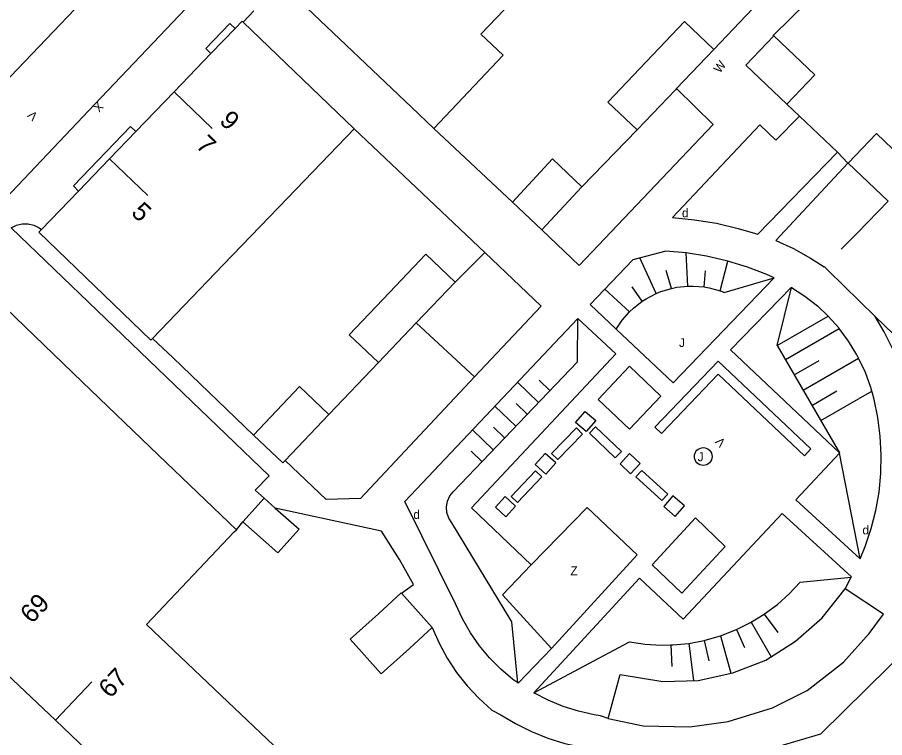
# Model space of a CAD drawing. Extents: x 134999 to 136502, y 457398 to 459002.
# Drawn here: x 135044.97 to 135094.16, y 458158.26 to 458199.12 of the extents above; entities that cross this region are included whole.
import ezdxf

# ---------------------------------------------------------------- set-up
doc = ezdxf.new("R2010")
doc.units = 0
for name, color, linetype in [('RI_DGTB_15', 7, 'Continuous'), ('RI_DGTB_18', 7, 'Continuous'), ('RI_DGTB_19', 7, 'Continuous'), ('RI_DGTB_2', 7, 'Continuous'), ('RI_DGTB_29', 7, 'Continuous'), ('RI_DGTB_30', 7, 'Continuous'), ('RI_DGTB_31', 7, 'Continuous'), ('RI_DGTB_32', 7, 'Continuous'), ('RI_DGTB_35', 7, 'Continuous'), ('RI_DGTB_36', 7, 'Continuous'), ('RI_DGTB_48', 7, 'Continuous'), ('RI_DGTB_5', 7, 'Continuous'), ('RI_DGTB_53', 7, 'Continuous'), ('RI_DGTB_54', 7, 'Continuous'), ('RI_DGTB_6', 7, 'Continuous'), ('RI_DGTB_7', 7, 'Continuous')]:
    doc.layers.add(name, color=color, linetype=linetype)

msp = doc.modelspace()

# ---------------------------------------------------------------- linework, layer by layer
at = {"layer": 'RI_DGTB_15'}
for p, q in [((135053.866, 458194.902), (135056.028, 458192.822)), ((135050.201, 458191.094), (135052.363, 458189.014)), ((135047.126, 458159.25), (135049.195, 458161.424))]:
    msp.add_line(p, q, dxfattribs=at)
at = {"layer": 'RI_DGTB_18'}
for p, q in [((135082.998, 458183.874), (135082.894, 458185.756)), ((135081.195, 458183.452), (135080.273, 458185.473)), ((135084.826, 458183.607), (135085.257, 458185.293)), ((135082.075, 458183.747), (135081.761, 458184.765)), ((135083.929, 458183.826), (135083.992, 458184.741)), ((135080.409, 458183.014), (135079.83, 458183.826)), ((135088.065, 458180.507), (135088.877, 458183.806)), ((135079.689, 458182.415), (135078.287, 458183.698)), ((135088.065, 458180.507), (135090.949, 458182.176)), ((135088.53, 458179.704), (135091.579, 458181.469)), ((135088.065, 458180.507), (135091.588, 458174.421)), ((135089.031, 458178.839), (135090.442, 458179.656)), ((135089.532, 458177.973), (135092.68, 458179.795)), ((135074.527, 458177.277), (135073.332, 458178.421)), ((135075.169, 458177.948), (135074.558, 458178.532)), ((135090.033, 458177.108), (135091.444, 458177.925)), ((135090.534, 458176.242), (135093.437, 458177.922)), ((135073.244, 458175.936), (135072.058, 458177.071)), ((135073.886, 458176.607), (135073.254, 458177.212)), ((135071.962, 458174.595), (135070.784, 458175.722)), ((135072.603, 458175.266), (135071.977, 458175.865)), ((135071.32, 458173.925), (135070.703, 458174.515)), ((135092.77, 458168.41), (135091.602, 458174.391)), ((135087.325, 458165.26), (135088.106, 458164.233)), ((135086.59, 458164.808), (135087.722, 458162.85)), ((135085.764, 458164.392), (135086.218, 458163.376)), ((135083.048, 458163.609), (135083.314, 458161.492)), ((135083.926, 458163.774), (135084.178, 458162.618)), ((135084.841, 458164.033), (135085.432, 458161.916)), ((135082.035, 458163.516), (135082.085, 458162.304))]:
    msp.add_line(p, q, dxfattribs=at)
for points in [[(135078.93, 458181.431), (135079.273, 458181.939), (135079.689, 458182.415), (135079.907, 458182.621), (135080.409, 458183.014), (135080.639, 458183.162), (135081.195, 458183.452), (135081.471, 458183.564), (135082.075, 458183.747), (135082.37, 458183.807), (135082.998, 458183.874), (135083.303, 458183.878), (135083.929, 458183.826), (135084.214, 458183.775), (135084.826, 458183.607), (135084.944, 458183.565), (135085.06, 458183.52), (135087.89, 458184.35)], [(135073.355, 458161.361), (135073.01, 458164.82), (135069.61, 458170.44), (135069.437, 458170.718), (135069.336, 458171.029), (135069.313, 458171.355), (135069.37, 458171.678), (135069.503, 458171.977), (135069.68, 458172.21), (135076.73, 458179.581), (135076.76, 458182.03)], [(135091.602, 458174.391), (135091.6, 458174.4), (135091.588, 458174.421)], [(135074.26, 458160.81), (135079.69, 458163.69), (135080.582, 458163.559), (135081.482, 458163.508), (135082.035, 458163.516), (135082.145, 458163.521), (135083.048, 458163.609), (135083.926, 458163.774), (135083.971, 458163.785), (135084.841, 458164.033), (135084.935, 458164.065), (135085.764, 458164.392), (135086.556, 458164.787), (135087.325, 458165.26), (135087.347, 458165.275), (135088.071, 458165.817), (135088.743, 458166.42), (135089.36, 458167.08), (135092.258, 458167.358)]]:
    msp.add_lwpolyline(points, dxfattribs=at)
at = {"layer": 'RI_DGTB_19'}
msp.add_lwpolyline([(135074.11, 458168.07), (135072.48, 458166.36), (135075.266, 458163.325)], dxfattribs=at)
at = {"layer": 'RI_DGTB_2'}
for p, q in [((135073.009, 458200), (135071.265, 458198.165)), ((135064.079, 458192.794), (135057.779, 458198.858)), ((135064.079, 458192.794), (135060.316, 458188.885)), ((135060.316, 458188.885), (135056.651, 458185.077)), ((135052.628, 458180.898), (135056.651, 458185.077)), ((135044.31, 458182.62), (135048.653, 458178.447)), ((135048.653, 458178.447), (135052.98, 458174.289)), ((135052.98, 458174.289), (135057.39, 458170.051)), ((135056.537, 458160.646), (135052.29, 458164.67)), ((135060.782, 458156.624), (135056.537, 458160.646)), ((135051.361, 458155.215), (135047.126, 458159.25))]:
    msp.add_line(p, q, dxfattribs=at)
for points in [[(135061.038, 458200), (135067.327, 458194.022)], [(135057.779, 458198.858), (135057.724, 458198.911), (135057.321, 458198.493)], [(135057.321, 458198.493), (135055.949, 458197.066)], [(135055.949, 458197.066), (135053.866, 458194.902)], [(135051.694, 458192.646), (135053.866, 458194.902)], [(135050.201, 458191.094), (135051.694, 458192.646)], [(135050.201, 458191.094), (135048.442, 458189.266)], [(135048.442, 458189.266), (135046.341, 458187.084)], [(135052.628, 458180.898), (135052.549, 458180.816), (135046.194, 458186.931), (135046.341, 458187.084)], [(135052.29, 458164.67), (135057.27, 458169.93), (135057.39, 458170.051)], [(135047.126, 458159.25), (135044.381, 458161.867)]]:
    msp.add_lwpolyline(points, dxfattribs=at)
at = {"layer": 'RI_DGTB_31'}
for points in [[(135077.23, 458175.62), (135076.63, 458176.14), (135077.18, 458176.77), (135077.78, 458176.25), (135077.23, 458175.62)], [(135074.94, 458173.21), (135075.51, 458173.84), (135074.91, 458174.38), (135074.34, 458173.75), (135074.94, 458173.21)], [(135079.69, 458174.37), (135079.15, 458173.79), (135079.75, 458173.23), (135080.29, 458173.81), (135079.69, 458174.37)], [(135082.15, 458171.97), (135081.63, 458171.37), (135082.28, 458170.81), (135082.8, 458171.41), (135082.15, 458171.97)], [(135072.68, 458170.79), (135073.23, 458171.4), (135072.63, 458171.94), (135072.08, 458171.33), (135072.68, 458170.79)]]:
    msp.add_lwpolyline(points, dxfattribs=at)
msp.add_circle((135083.868, 458174.207), 0.504, dxfattribs=at)
at = {"layer": 'RI_DGTB_32'}
for points in [[(135077.42, 458175.54), (135078.88, 458174.13), (135079.227, 458174.49), (135077.767, 458175.9), (135077.42, 458175.54)], [(135075.62, 458174.03), (135077.03, 458175.48), (135076.672, 458175.829), (135075.262, 458174.379), (135075.62, 458174.03)], [(135073.33, 458171.59), (135074.72, 458173.05), (135074.358, 458173.395), (135072.968, 458171.935), (135073.33, 458171.59)], [(135080.05, 458173.05), (135081.52, 458171.71), (135081.857, 458172.08), (135080.387, 458173.42), (135080.05, 458173.05)]]:
    msp.add_lwpolyline(points, dxfattribs=at)
at = {"layer": 'RI_DGTB_48'}
msp.add_line((135057.39, 458170.051), (135057.76, 458170.5), dxfattribs=at)
for points in [[(135092.592, 458186.878), (135094.362, 458188.693)], [(135092.592, 458186.878), (135091.7, 458185.964)], [(135099.55, 458183.78), (135098.36, 458184.88), (135094.66, 458181.14), (135093.62, 458182.16)]]:
    msp.add_lwpolyline(points, dxfattribs=at)
at = {"layer": 'RI_DGTB_5'}
for points in [[(135071.265, 458198.165), (135072.523, 458196.969), (135068.585, 458192.826)], [(135068.585, 458192.826), (135067.327, 458194.022)]]:
    msp.add_lwpolyline(points, dxfattribs=at)
at = {"layer": 'RI_DGTB_53'}
for p, q in [((135087.045, 458200), (135084.473, 458197.3)), ((135057.779, 458198.858), (135058.39, 458199.49)), ((135089.335, 458193.524), (135088.604, 458194.197)), ((135091.49, 458191.47), (135089.335, 458193.524)), ((135064.079, 458192.794), (135071.49, 458185.79)), ((135071.49, 458185.79), (135069.802, 458184.101)), ((135090.777, 458184.925), (135090.73, 458184.97)), ((135067.595, 458181.785), (135070.89, 458178.72)), ((135062.642, 458176.585), (135065.449, 458179.533)), ((135091.91, 458166.71), (135092.258, 458167.358))]:
    msp.add_line(p, q, dxfattribs=at)
for points in [[(135054.883, 458200), (135049.37, 458194.19), (135043.29, 458187.81), (135040, 458190.93), (135040.72, 458191.66), (135040.743, 458191.685)], [(135048.629, 458200), (135042.55, 458193.64), (135040.743, 458191.685)], [(135087.879, 458198.071), (135087.84, 458198.1), (135089.778, 458200)], [(135082.359, 458195.081), (135084.43, 458193.05), (135076.83, 458185.05), (135074.715, 458187.06)], [(135089.335, 458193.524), (135087.98, 458192.15), (135087.08, 458193.03), (135082.12, 458187.77), (135083.375, 458187.643), (135084.62, 458187.437), (135085.85, 458187.152), (135086.97, 458186.82), (135091.49, 458191.47)], [(135068.585, 458192.826), (135073.045, 458188.631)], [(135091.49, 458191.47), (135092.07, 458190.85), (135087.98, 458186.46), (135088.983, 458186), (135089.95, 458185.469), (135090.73, 458184.97)], [(135044.622, 458187.175), (135044.92, 458187.331), (135045.245, 458187.412), (135045.581, 458187.414), (135045.908, 458187.337), (135046.208, 458187.185), (135046.341, 458187.084)], [(135044.622, 458187.175), (135059.26, 458173.12), (135058.45, 458172.29), (135058.96, 458171.84)], [(135071.49, 458185.79), (135074.68, 458182.73), (135070.89, 458178.72)], [(135087.89, 458184.35), (135087.474, 458184.532), (135086.379, 458184.95), (135085.257, 458185.293), (135085.191, 458185.311), (135084.05, 458185.573), (135082.894, 458185.756), (135081.75, 458185.86), (135079.88, 458185.37), (135077.46, 458182.83), (135078.93, 458181.431)], [(135093.62, 458182.16), (135090.949, 458184.758)], [(135087.89, 458184.35), (135082.17, 458178.38), (135078.93, 458181.431)], [(135091.588, 458174.421), (135085.42, 458180.26), (135088.87, 458183.81), (135088.877, 458183.806)], [(135088.877, 458183.806), (135089.632, 458183.31), (135090.341, 458182.749), (135090.949, 458182.176)], [(135099.55, 458183.78), (135095.06, 458179.22), (135094.634, 458180.264), (135094.135, 458181.274), (135093.62, 458182.16)], [(135073.355, 458161.361), (135073.079, 458161.564), (135072.389, 458162.142), (135071.753, 458162.779), (135071.175, 458163.47), (135070.661, 458164.209), (135070.215, 458164.991), (135069.84, 458165.81), (135066.94, 458171.65), (135076.75, 458182.04), (135076.76, 458182.03)], [(135076.76, 458182.03), (135078.91, 458180.03), (135070.72, 458171.29), (135074.11, 458168.07)], [(135092.77, 458168.41), (135093.058, 458169.112), (135093.395, 458170.117), (135093.657, 458171.144), (135093.839, 458172.188), (135093.943, 458173.243), (135093.967, 458174.302), (135093.911, 458175.361), (135093.775, 458176.412), (135093.56, 458177.45), (135093.53, 458177.58), (135093.485, 458177.751), (135093.437, 458177.922), (135093.374, 458178.128), (135093.064, 458178.977), (135092.68, 458179.795), (135092.584, 458179.974), (135092.115, 458180.744), (135091.579, 458181.469), (135091.552, 458181.502), (135090.949, 458182.176)], [(135058.364, 458175.427), (135053.8, 458179.8), (135052.628, 458180.898)], [(135079.69, 458175.76), (135077.91, 458177.45), (135079.68, 458179.33), (135081.46, 458177.64), (135079.69, 458175.76)], [(135081.5, 458175.51), (135081.13, 458175.87), (135084.71, 458179.62), (135089.98, 458174.65), (135089.62, 458174.25), (135084.71, 458178.88), (135081.5, 458175.51)], [(135070.89, 458178.72), (135064.43, 458171.83), (135062.48, 458171.76), (135060.165, 458173.985)], [(135091.602, 458174.391), (135091.61, 458174.4), (135091.588, 458174.421)], [(135092.77, 458168.41), (135089.12, 458171.75), (135091.602, 458174.391)], [(135066.759, 458166.449), (135067.43, 458166.94), (135066.65, 458168.37), (135065.63, 458169.98), (135059.594, 458171.279)], [(135074.11, 458168.07), (135077.28, 458171.32), (135080.12, 458168.63), (135075.266, 458163.325)], [(135092.258, 458167.358), (135092.27, 458167.38), (135088.34, 458170.98), (135082.73, 458164.98), (135080.26, 458167.31), (135074.26, 458160.81)], [(135080.97, 458168.07), (135082.66, 458166.45), (135085.12, 458169.1), (135083.43, 458170.72), (135080.97, 458168.07)], [(135068.49, 458164.5), (135068.884, 458163.616), (135069.35, 458162.767), (135069.884, 458161.959), (135070.483, 458161.198), (135071.143, 458160.49), (135071.88, 458159.82), (135072.36, 458159.57), (135073.222, 458159.053), (135074.122, 458158.607), (135075.055, 458158.233), (135076.014, 458157.935), (135076.994, 458157.714), (135077.989, 458157.571), (135078.397, 458157.536)], [(135075.266, 458163.325), (135073.37, 458161.35), (135073.355, 458161.361)], [(135090.786, 458149.537), (135090.034, 458150.255), (135090.069, 458150.292), (135083.61, 458156.44), (135090.54, 458158.47), (135095.71, 458163.58), (135099.104, 458160.394), (135099.17, 458160.46), (135100.246, 458159.434)], [(135078.47, 458159.35), (135078.04, 458159.5), (135077.683, 458159.557), (135076.789, 458159.757), (135075.917, 458160.034), (135075.071, 458160.386), (135074.26, 458160.81)]]:
    msp.add_lwpolyline(points, dxfattribs=at)
at = {"layer": 'RI_DGTB_54'}
msp.add_line((135076.99, 458189.517), (135080.12, 458192.732), dxfattribs=at)
at = {"layer": 'RI_DGTB_6'}
for p, q in [((135082.359, 458195.081), (135084.473, 458197.3)), ((135082.359, 458195.081), (135082.296, 458195.015)), ((135074.715, 458187.06), (135076.99, 458189.517)), ((135073.045, 458188.631), (135074.715, 458187.06)), ((135066.068, 458183.515), (135068.137, 458185.687)), ((135069.802, 458184.101), (135067.595, 458181.785)), ((135067.595, 458181.785), (135065.449, 458179.533)), ((135060.165, 458173.985), (135062.642, 458176.585)), ((135057.76, 458170.5), (135058.96, 458171.84)), ((135058.96, 458171.84), (135059.594, 458171.279)), ((135068.49, 458164.5), (135066.759, 458166.449))]:
    msp.add_line(p, q, dxfattribs=at)
for points in [[(135084.473, 458197.3), (135082.807, 458198.887), (135080.63, 458196.603)], [(135087.879, 458198.071), (135086.291, 458196.408), (135088.604, 458194.197)], [(135088.604, 458194.197), (135090.192, 458195.86), (135087.879, 458198.071)], [(135080.63, 458196.603), (135078.454, 458194.319), (135080.12, 458192.732)], [(135080.12, 458192.732), (135082.296, 458195.015)], [(135094.362, 458188.693), (135092.095, 458190.859), (135093.691, 458192.53), (135095.964, 458190.358)], [(135076.99, 458189.517), (135075.32, 458191.088), (135073.045, 458188.631)], [(135069.802, 458184.101), (135068.137, 458185.687)], [(135090.949, 458184.758), (135090.777, 458184.925)], [(135066.068, 458183.515), (135063.784, 458181.118), (135065.449, 458179.533)], [(135062.642, 458176.585), (135060.978, 458178.171), (135058.364, 458175.427)], [(135058.364, 458175.427), (135060.028, 458173.841), (135060.165, 458173.985)], [(135059.594, 458171.279), (135060.95, 458170.08), (135059.75, 458168.74), (135057.76, 458170.5)], [(135078.47, 458159.35), (135080.47, 458158.92), (135083.11, 458158.88), (135085.29, 458159.17), (135087.79, 458159.95), (135089.76, 458160.93), (135091.82, 458162.54), (135093.28, 458164.16), (135094.09, 458165.27), (135091.91, 458166.71)], [(135078.47, 458159.35), (135079.16, 458161.85), (135081.57, 458161.44), (135083.59, 458161.5), (135085.54, 458161.94), (135087.41, 458162.65), (135089.1, 458163.73), (135090.62, 458165.06), (135091.91, 458166.71)], [(135066.759, 458166.449), (135066.74, 458166.47), (135065.46, 458165.28)], [(135067.21, 458163.31), (135065.6, 458161.88), (135063.85, 458163.85), (135065.46, 458165.28)], [(135067.21, 458163.31), (135068.49, 458164.5)]]:
    msp.add_lwpolyline(points, dxfattribs=at)
at = {"layer": 'RI_DGTB_7'}
for p, q in [((135055.655, 458197.351), (135057.027, 458198.778)), ((135057.027, 458198.778), (135057.321, 458198.493)), ((135055.949, 458197.066), (135055.655, 458197.351))]:
    msp.add_line(p, q, dxfattribs=at)
for points in [[(135048.15, 458189.555), (135051.395, 458192.927), (135051.694, 458192.646)], [(135048.442, 458189.266), (135048.15, 458189.555)]]:
    msp.add_lwpolyline(points, dxfattribs=at)

# ---------------------------------------------------------------- texts
at = {"layer": 'RI_DGTB_29'}
for p in [(135082.66, 458187.78), (135067.43, 458170.67), (135092.9, 458169.79)]:
    msp.add_text('d', height=0.5, rotation=359.9997, dxfattribs=at).set_placement(p)
at = {"layer": 'RI_DGTB_30'}
for s, rotation, p in [('W', 53.13, (135084.816, 458195.916)), ('X', 226.3781, (135049.542, 458194.371)), ('V', 136.4309, (135046.174, 458193.569)), ('V', 133.6665, (135085.174, 458175.032))]:
    msp.add_text(s, height=0.5, rotation=rotation, dxfattribs=at).set_placement(p)
at = {"layer": 'RI_DGTB_31'}
for p in [(135082.5, 458180.42), (135083.55, 458173.94)]:
    msp.add_text('J', height=0.5, rotation=359.9997, dxfattribs=at).set_placement(p)
at = {"layer": 'RI_DGTB_32'}
msp.add_text('Z', height=0.5, dxfattribs=at).set_placement((135076.337, 458167.476))
at = {"layer": 'RI_DGTB_35'}
for s, rotation, p in [('9', 316.0984, (135056.377, 458193.183)), ('5', 316.0901, (135051.372, 458187.986))]:
    msp.add_text(s, height=1.054, rotation=rotation, dxfattribs=at).set_placement(p)
at = {"layer": 'RI_DGTB_36'}
for s, rotation, p in [('7', 316.0901, (135055.039, 458191.794)), ('69', 46.4237, (135045.791, 458164.677)), ('67', 46.4237, (135050.234, 458160.443))]:
    msp.add_text(s, height=1.054, rotation=rotation, dxfattribs=at).set_placement(p)

doc.saveas('drawing.dxf')
